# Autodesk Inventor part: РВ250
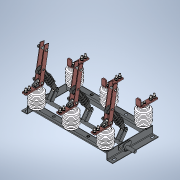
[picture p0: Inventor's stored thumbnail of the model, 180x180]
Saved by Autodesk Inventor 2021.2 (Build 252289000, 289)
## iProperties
Created: 1900-01
Part Number: РВ250
Material: Типовые
Description: STEP AP242
Document SubType Name: Modeling
Designer: pc
Density: 1 g/cm^3
Appearance: По умолчанию
Company: UNSPECIFIED
Title: ÐÂ250
Author: UNSPECIFIED
Revision Number: ANYUNSPECIFIED
Sending System: C3D Toolkit
Preprocessor: C3D Converter
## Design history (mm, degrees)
feature "БазТело1"
feature "БазТело2"
feature "БазТело3"
feature "БазТело4"
feature "БазТело5"
feature "Составной1"
node "Твердое тело1"
node "Твердое тело2"
node "Твердое тело3"
node "Твердое тело4"
node "Твердое тело5"
body "SRF1"
